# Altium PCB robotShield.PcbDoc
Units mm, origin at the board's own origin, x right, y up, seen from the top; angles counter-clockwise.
Board outline 152.4 x 101.6 mm, 2 copper layers (Top Layer, Bottom Layer); 72 components, 52 nets, 214 pads, 0 vias.
Unrouted connection lines stored in the file: 132.
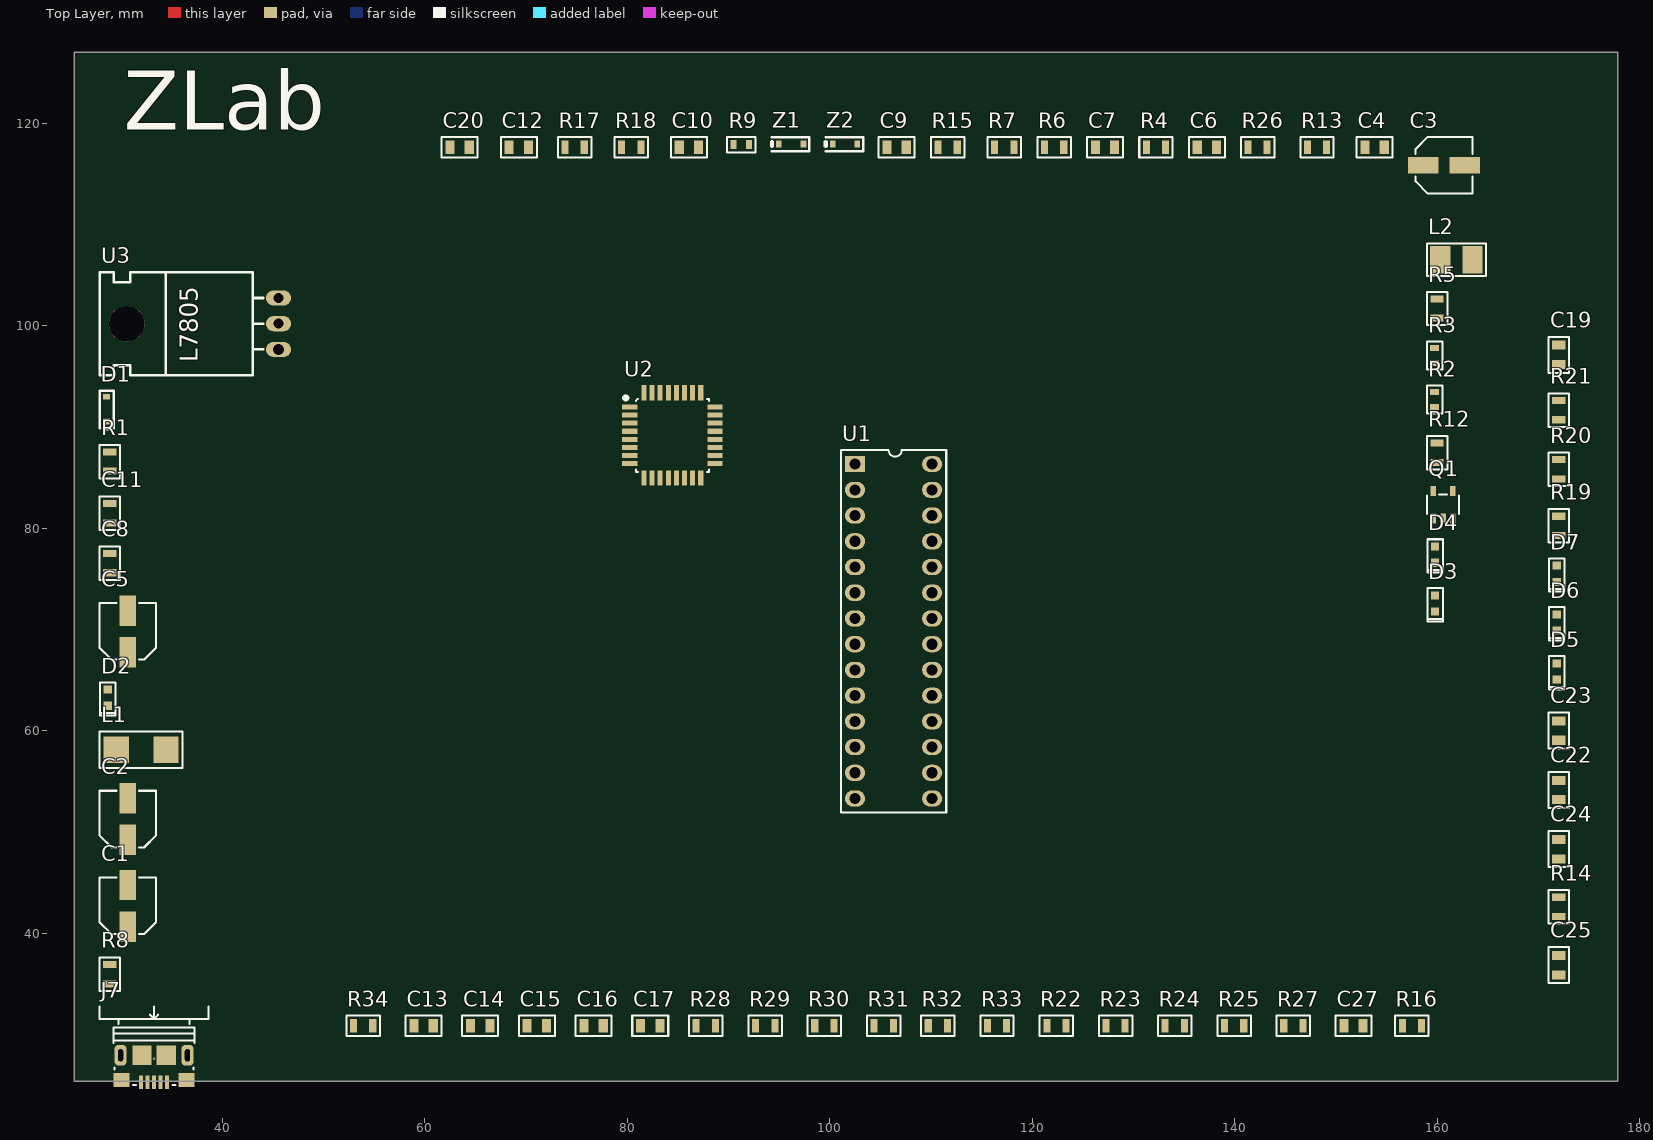
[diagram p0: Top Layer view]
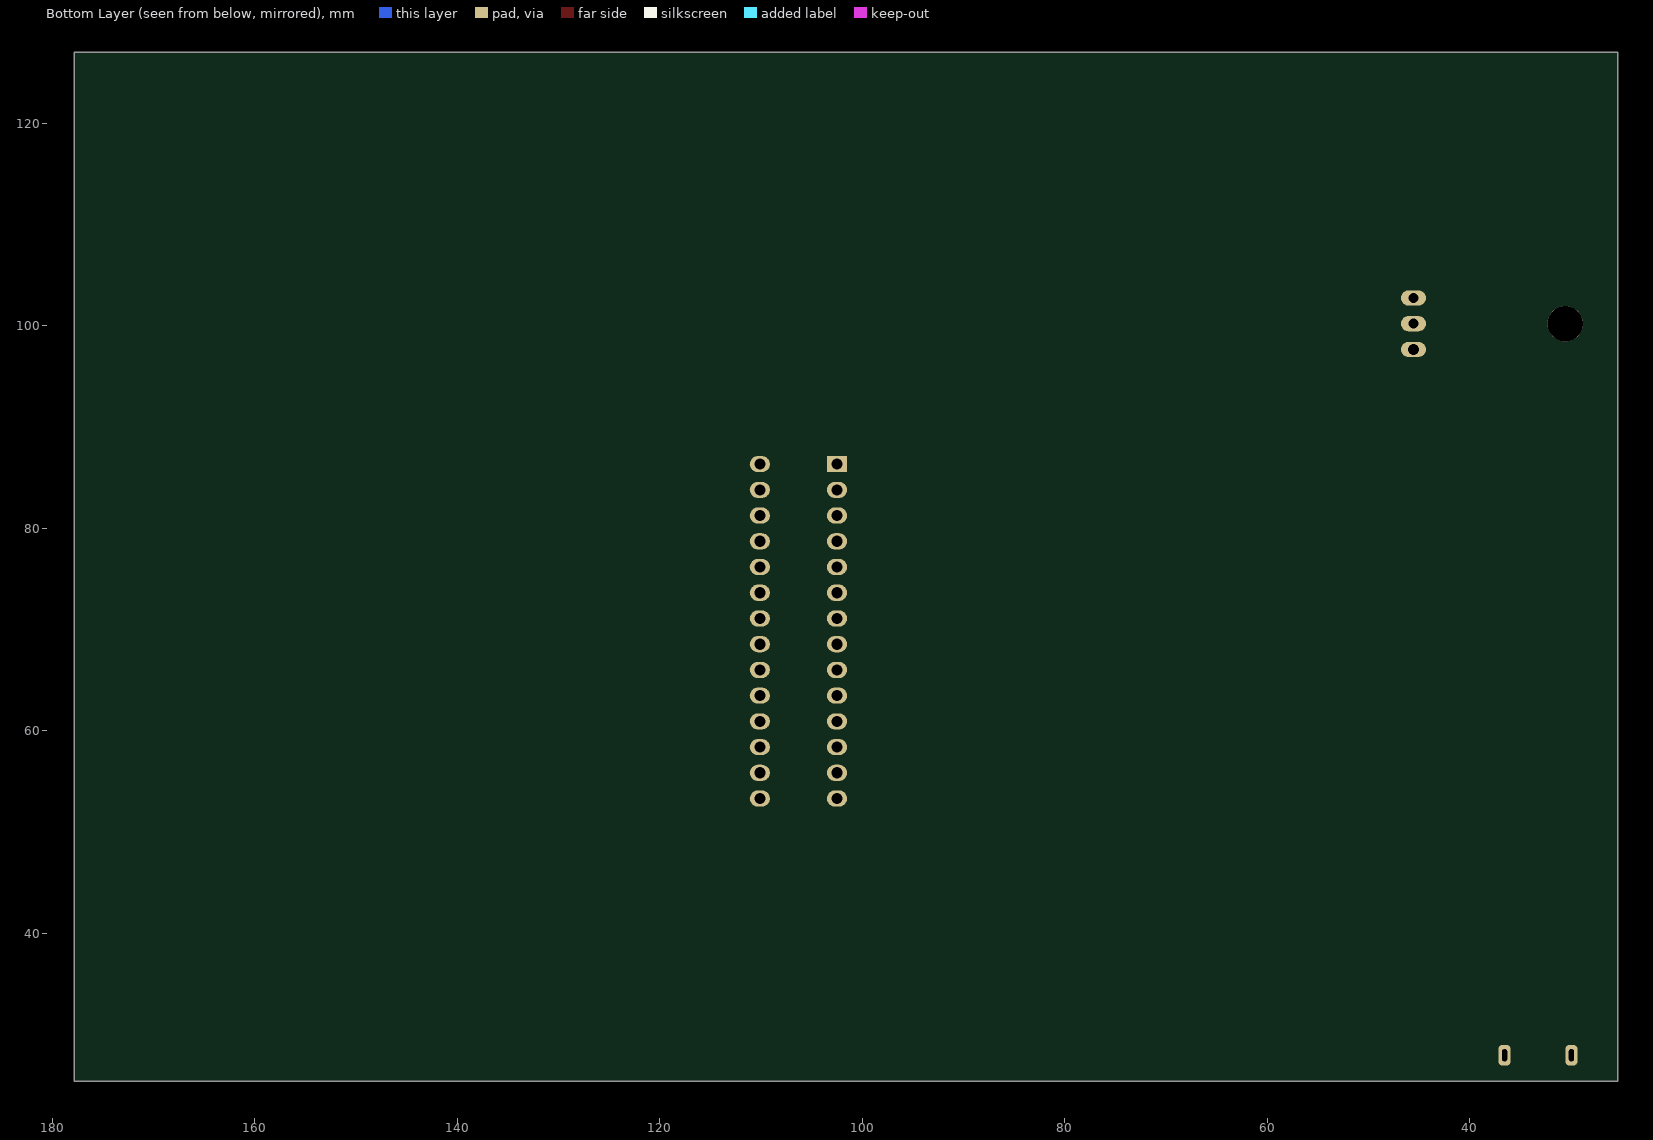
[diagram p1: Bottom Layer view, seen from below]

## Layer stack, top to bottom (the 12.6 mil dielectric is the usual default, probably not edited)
Top Solder: solder mask 0.0102, Solder Resist, Dk 3.5
Top Layer: signal copper 0.0356
Dielectric 1: dielectric 0.32, FR-4, Dk 4.8
Bottom Layer: signal copper 0.0356
Bottom Solder: solder mask 0.0102, Solder Resist, Dk 3.5

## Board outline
25.4,25.4 177.8,25.4 177.8,127 25.4,127

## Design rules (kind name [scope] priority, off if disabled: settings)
Clearance [All] p1: gap=0.254 ignorepadtopadclearanceinfootprint=FALSE
PolygonConnect [All] p1: connectstyle=Relief reliefconductorwidth=0.254 reliefentries=4 polygonreliefangle="90 Angle" airgapwidth=0.254
RoutingVias [All] p1: holewidth=0.711 width=1.27 viastyle="Through Hole" minholewidth=0.711 minwidth=1.27 maxholewidth=0.711 maxwidth=1.27
SolderMaskExpansion [All] p1: expansion=0.102 istentingtop=FALSE
Width [All] p1: maxlimit=0.254 minlimit=0.254 preferedwidth=0.254
30 further rules are at their usual default settings.

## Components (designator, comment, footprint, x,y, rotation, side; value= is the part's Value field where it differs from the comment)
C1 "100u / 10V" C_ALU_C_SIZE 30.683,42.723 r90 top
C2 "100u / 10V" C_ALU_C_SIZE 30.683,51.283 r90 top
C3 "10uF / 16V" C_ALU_C_SIZE 160.655,115.849 r0 top
C4 "100n" C0805 153.797,117.627 r0 top
C5 "10u" C_ALU_C_SIZE 30.683,69.825 r90 top
C6 "100n" C0805 137.236,117.627 r0 top
C7 "1u" C0805 127.178,117.627 r0 top
C8 "100nF" R0805 28.905,76.556 r90 top
C9 "18p" C0805 106.604,117.627 r0 top
C10 "18p" C0805 86.081,117.627 r0 top
C11 "100nF" R0805 28.905,81.483 r90 top
C12 "100n" C0805 69.291,117.627 r0 top
C13 "Cap" C0805 59.893,30.886 r0 top value=100nF
C14 "Cap" C0805 65.481,30.886 r0 top value=100nF
C15 "Cap" C0805 71.069,30.886 r0 top value=100nF
C16 "Cap" C0805 76.683,30.886 r0 top value=100nF
C17 "Cap" C0805 82.271,30.886 r0 top value=100nF
C19 "10uF / 16V" C0805 171.983,97.13 r90 top
C20 "100n" C0805 63.449,117.627 r0 top
C22 "10uF / 16V" C0805 171.983,54.153 r90 top
C23 "100n" C0805 171.983,60.02 r90 top
C24 "100n" C0805 171.983,48.311 r90 top
C25 "18p" C0805 171.983,36.855 r90 top
C27 "18p" C0805 151.714,30.886 r0 top
D1 "Diode" SOD323 28.6,91.77 r90 top
D2 "Power" LED_0603 28.702,63.271 r90 top
D3 "" LED_0603 159.766,72.568 r90 top
D4 "" LED_0603 159.766,77.394 r90 top
D5 "GREEN" LED_0603 171.78,65.862 r90 top
D6 "YELLOW" LED_0603 171.78,70.688 r90 top
D7 "RED" LED_0603 171.78,75.514 r90 top
J7 "" 10118193 33.274,27.965 r180 top
L1 "2u2 / 2A" ABM7_v1_1_BIG 32.004,58.141 r180 top
L2 "Ferrite Bead" C1210_IND 161.874,106.528 r180 top
Q1 "BC817" DBV_SOT_23_5 160.553,82.321 r90 top
R1 "560" R0805 28.905,86.589 r90 top
R2 "560R" R0603 159.715,92.71 r90 top
R3 "560R" R0603 159.715,97.053 r90 top
R4 "10k" R0805 132.207,117.627 r0 top
R5 "1K" R0805 159.969,101.702 r90 top value=3.9R
R6 "22R" R0805 122.149,117.627 r0 top
R7 "22R" R0805 117.221,117.627 r0 top
R8 "0R" R0805 28.905,35.966 r90 top
R9 "1M" R0603 91.262,117.881 r0 top
R12 "1K" R0805 159.969,87.452 r90 top
R13 "10K" R0805 148.107,117.627 r0 top
R14 "10k" R0805 171.983,42.621 r90 top
R15 "Res1" R0805 111.633,117.627 r0 top value=4.7k
R16 "1M" R0805 157.48,30.886 r0 top
R17 "4.7K" R0805 74.803,117.627 r0 top
R18 "4.7K" R0805 80.391,117.627 r0 top
R19 "560R" R0805 171.983,80.239 r90 top
R20 "560R" R0805 171.983,85.827 r90 top
R21 "560R" R0805 171.983,91.669 r90 top
R22 "0.22OHM-1_4W-1%(0805)" R0805 122.377,30.886 r0 top
R23 "0.22OHM-1_4W-1%(0805)" R0805 128.219,30.886 r0 top
R24 "0.22OHM-1_4W-1%(0805)" R0805 134.061,30.886 r0 top
R25 "0.22OHM-1_4W-1%(0805)" R0805 139.929,30.886 r0 top
R26 "0R" R0805 142.24,117.627 r0 top
R27 "0.22OHM-1_4W-1%(0805)" R0805 145.771,30.886 r0 top
R28 "3.3K" R0805 87.757,30.886 r0 top
R29 "" R0805 93.624,30.886 r0 top value=1K
R30 "" R0805 99.466,30.886 r0 top value=1K
R31 "" R0805 105.334,30.886 r0 top value=1K
R32 "" R0805 110.668,30.886 r0 top value=1K
R33 "" R0805 116.51,30.886 r0 top value=1K
R34 "2.4K" R0805 53.924,30.886 r0 top
U1 "ATMEGA328P-PU" 28_DIP_7.62mm 102.489,86.335 r0 top
U2 "ATMEGA16U2-AU" TQFP32 84.455,89.179 r0 top
U3 "LM7805" L7805 45.568,97.663 r90 top
Z1 "CG0603MLC-05E" SOD323 96.19,117.932 r0 top
Z2 "CG0603MLC-05E" SOD323 101.498,117.932 r0 top

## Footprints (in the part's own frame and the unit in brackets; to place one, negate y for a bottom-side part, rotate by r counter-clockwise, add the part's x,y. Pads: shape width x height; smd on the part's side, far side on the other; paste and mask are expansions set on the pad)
28_DIP_7.62mm [mm] "Creator MM"
  rect 2x1.6 hole 1.1: 1(0,0)
  oval 2x1.6 hole 1.1: 2(0,-2.54) 3(0,-5.08) 4(0,-7.62) 5(0,-10.16) 6(0,-12.7) 7(0,-15.24) 8(0,-17.78) 9(0,-20.32) 10(0,-22.86) 11(0,-25.4) 12(0,-27.94) 13(0,-30.48) 14(0,-33.02) 15(7.62,-33.02) 16(7.62,-30.48) 17(7.62,-27.94) 18(7.62,-25.4) 19(7.62,-22.86) 20(7.62,-20.32) 21(7.62,-17.78) 22(7.62,-15.24) 23(7.62,-12.7) 24(7.62,-10.16) 25(7.62,-7.62) 26(7.62,-5.08) 27(7.62,-2.54) 28(7.62,0)
  silkscreen extent -1.39,-34.41 9.01,1.39, body extent -0.13,-34.48 7.75,1.46, height 6.15
10118193 [mm] "Creator MM"
  rect 0.4x1.35 smd mask+0.05: 1(-1.3,2.675) 2(-0.65,2.675) 3(0,2.675) 4(0.65,2.675) 5(1.3,2.675)
  rect 1.6x1.4 smd: 6(-3.2,2.45) 7(3.2,2.45)
  rrect60% 1.2x2 hole 0.5 slot 1.2 at 90 deg: 8(-3.3,0) 9(3.3,0)
  rect 1.9x1.9 smd paste-10: 10(-1.2,0) 11(1.2,0)
  silkscreen extent -5.4,-4.8 5.4,2.95, body extent -3.93,-2.76 3.93,2.9, height 2.85
ABM7_v1_1_BIG [mm] "Made longer for hand soldering"
  rect 2.5x2.6 smd: 1(-2.45,0) 2(2.45,0)
  silkscreen extent -4.1,-1.8 4.1,1.8, body extent -3.1,-1.85 3.1,1.85, height 1.45
C0805 [mm]
  rect 0.9x1.3 smd: 1(-0.95,0) 2(0.95,0)
  silkscreen extent -1.78,-1.02 1.78,1.02, body extent -1,-0.6 1,0.6, height 1.5
C1210_IND [mm] "INDUCTOR"
  rect 2x2.7 smd: 1(-1.6,0) 2(1.6,0)
  silkscreen extent -2.9,-1.6 2.9,1.6, body extent -1.6,-1.25 1.6,1.25, height 2.5
C_ALU_C_SIZE [mm] "Creator MM"
  rect 3x1.6 smd: 1(-2.05,0) 2(2.05,0)
  silkscreen extent -2.8,-2.8 2.8,2.8, body extent -3,-2.65 3,2.65, height 6.42
DBV_SOT_23_5 [mm]
  rect 1x0.55 smd: 1(-1.35,0.95) 2(-1.35,0) 3(-1.35,-0.95) 4(1.35,-0.95) 5(1.35,0.95)
  silkscreen extent -0.9,-1.59 1.02,1.59, body extent -1.65,-1.69 1.78,1.69, height 1.45
L7805 [mm]
  oval 1.5x2.5 hole 1.1 paste-2539.97 mask+0.102: 1(0,0)
  oval 1.5x2.5 hole 1 paste-2539.97 mask+0.102: 2(2.54,0)
  oval 1.5x2.5 hole 1 paste-2539.97 mask+0.051: 3(5.08,0)
  round 3.5 hole 3.5 unplated paste-2539.97: ""(2.54,14.986)
  silkscreen extent -2.55,1.52 7.61,17.66
LED_0603 [mm]
  rect 0.8x0.8 smd: 1(-0.8,0) 2(0.8,0)
  silkscreen extent -1.78,-0.76 1.52,0.76, body extent -0.85,-0.4 0.85,0.4, height 0.66
R0603 [mm]
  rect 0.6x0.9 smd: 1(-0.75,0) 2(0.75,0)
  silkscreen extent -1.4,-0.76 1.4,0.76, body extent -0.8,-0.42 0.8,0.42, height 0.8
R0805 [mm]
  rect 0.7x1.3 smd: 1(-0.95,0) 2(0.95,0)
  silkscreen extent -1.65,-1.02 1.65,1.02, body extent -1,-0.6 1,0.6, height 0.7
SOD323 [mil]
  rect 22x27 smd mask+3: 1(-48,0) 2(48,0)
  silkscreen extent -75,-28 71,28, body extent -49,-25 49,25, height 39
TQFP32 [mm] "Creator MM"
  rect 1.5x0.5 smd mask+0.06: 1(-4.2,2.8) 2(-4.2,2) 3(-4.2,1.2) 4(-4.2,0.4) 5(-4.2,-0.4) 6(-4.2,-1.2) 7(-4.2,-2) 8(-4.2,-2.8) 17(4.2,-2.8) 18(4.2,-2) 19(4.2,-1.2) 20(4.2,-0.4) 21(4.2,0.4) 22(4.2,1.2) 23(4.2,2) 24(4.2,2.8)
  rect 0.5x1.5 smd mask+0.06: 9(-2.8,-4.2) 10(-2,-4.2) 11(-1.2,-4.2) 12(-0.4,-4.2) 13(0.4,-4.2) 14(1.2,-4.2) 15(2,-4.2) 16(2.8,-4.2) 25(2.8,4.2) 26(2,4.2) 27(1.2,4.2) 28(0.4,4.2) 29(-0.4,4.2) 30(-1.2,4.2) 31(-2,4.2) 32(-2.8,4.2)
  silkscreen extent -4.7,-3.6 3.6,3.8, body extent -4.6,-4.6 4.6,4.6, height 1.2

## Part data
C1 C2: library part EEE-1AA101WR, "CAP ALUM 100UF 10V 20% SMD", Capacitance=100µF, ESR (Equivalent Series Resistance)=-, Lifetime @ Temp.="1000 Hrs @ 85°C", Manufacturer="Panasonic Electronic Components", Operating Temperature="-40°C ~ 85°C", Package / Case="Radial, Can - SMD", Ripple Current=50mA, Supplier Part Number 1=PCE3867CT-ND, Tolerance=±20%, Voltage Rating=10V
C3 C19 C22: library part C2012X5R1C106M, "CAP CER 10UF 16V 20% X5R 0805", Capacitance=10µF, Manufacturer="TDK Corporation", Manufacturer Part Number=C2012X5R1C106M/1.25, Operating Temperature="-55°C ~ 85°C", Package / Case="0805 (2012 Metric)", Ratings=-, Supplier Part Number 1=445-4115-1-ND, Temperature Coefficient=X5R, Tolerance=±20%, Voltage - Rated=16V
C4 C6 C12 C20 C23 C24: library part C2012X7R1H104K085AA, "CAP CER 0.1UF 50V 10% X7R 0805", Capacitance=0.1µF, Manufacturer="TDK Corporation", Operating Temperature="-55°C ~ 125°C", Package / Case="0805 (2012 Metric)", Ratings=-, Supplier Part Number 1=445-7534-1-ND, Temperature Coefficient=X7R, Tolerance=±10%, Voltage - Rated=50V
C5 R22 R23 R24 R25 R27 U3: Manufacturer Part=?
C7: library part C2012X5R1E105K125AA, "CAP CER 1UF 25V 10% X5R 0805", Capacitance=1µF, Manufacturer="TDK Corporation", Operating Temperature="-55°C ~ 85°C", Package / Case="0805 (2012 Metric)", Ratings=-, Supplier Part Number 1=445-1419-1-ND, Temperature Coefficient=X5R, Tolerance=±10%, Voltage - Rated=25V
C8 C11: library part 0.1u, Manufacturer Part=?
C9 C10 C25 C27: library part C0805C180J5GACTU, "CAP CER 18PF 50V 5% NP0 0805", Capacitance=18pF, Manufacturer=Kemet, Operating Temperature="-55°C ~ 125°C", Package / Case="0805 (2012 Metric)", Ratings=-, Supplier Part Number 1=399-1112-1-ND, Temperature Coefficient="C0G, NP0", Tolerance=±5%, Voltage - Rated=50V
C13 C14 C15 C16 C17: "Capacitor"
D1: "Default Diode"
D2: library part RED, Manufacturer Part=?
D3 D4: library part "LO L29K-H2K1-24-Z", "LED SMARTLED ORANGE 606NM 0603", Color=Orange, Current - Test=2mA, Luminous Flux @ Current - Test="25 mlm", Manufacturer="OSRAM Opto Semiconductors Inc", Millicandela Rating=6.3mcd, Package / Case="0603 (1608 Metric)", Supplier Part Number 1=475-2740-1-ND, Voltage - Forward (Vf) Typ=1.8V
D5 D6 D7: library part "LO L29K-H2K1-24-Z", Color=Orange, Current - Test=2mA, Luminous Flux @ Current - Test="25 mlm", Manufacturer="OSRAM Opto Semiconductors Inc", Millicandela Rating=6.3mcd, Package / Case="0603 (1608 Metric)", Supplier Part Number 1=475-2740-1-ND, Voltage - Forward (Vf) Typ=1.8V
J7: library part 10118193-0001LF, "CONN USB MICRO B RECPT SMT R/A", Manufacturer=FCI, Supplier Part Number 1=609-4616-1-ND
L1: library part L1210R2R2MDWIT, "FIXED IND 2.2UH 2A 80 MOHM SMD", Current - Saturation=-, Current Rating=2A, DC Resistance (DCR)="80 mOhm", Frequency - Self Resonant=190MHz, Frequency - Test=100kHz, Inductance=2.2µH, Manufacturer=Kemet, Operating Temperature="-40°C ~ 105°C", Package / Case="1210 (3225 Metric)", Supplier Device Package=1210, Supplier Part Number 1=399-9598-1-ND, Tolerance=±20%
L2: library part L1210R2R2MDWIT, Current - Saturation=-, Current Rating=2A, DC Resistance (DCR)="80 mOhm", Frequency - Self Resonant=190MHz, Frequency - Test=100kHz, Inductance=2.2µH, Manufacturer=Kemet, Operating Temperature="-40°C ~ 105°C", Package / Case="1210 (3225 Metric)", Supplier Device Package=1210, Supplier Part Number 1=399-9598-1-ND, Tolerance=±20%
Q1: library part NPN, "NPN Transistor"
R1: library part 10k, Manufacturer Part=?
R2 R3 R19 R20 R21 R28 R34: library part RC0805FR-07560RL, "RES SMD 560 OHM 1% 1/8W 0805", Manufacturer=Yageo, Operating Temperature="-55°C ~ 155°C", Package / Case="0805 (2012 Metric)", Power (Watts)="0.125W, 1/8W", Resistance (Ohms)=560, Supplier Device Package=0805, Supplier Part Number 1=311-560CRCT-ND, Temperature Coefficient=±100ppm/°C, Tolerance=±1%
R4 R14: library part RC0805FR-0710KL, "RES SMD 10K OHM 1% 1/8W 0805", Manufacturer=Yageo, Operating Temperature="-55°C ~ 155°C", Package / Case="0805 (2012 Metric)", Power (Watts)="0.125W, 1/8W", Supplier Device Package=0805, Supplier Part Number 1=311-10.0KCRCT-ND, Temperature Coefficient=±100ppm/°C, Tolerance=±1%
R5 R12 R13 R29 R30 R31 R32 R33: library part Res1, "Resistor"
R6 R7: library part RC0805FR-0722RL, "RES SMD 22 OHM 1% 1/8W 0805", Manufacturer=Yageo, Operating Temperature="-55°C ~ 155°C", Package / Case="0805 (2012 Metric)", Power (Watts)="0.125W, 1/8W", Resistance (Ohms)=22, Supplier Device Package=0805, Supplier Part Number 1=311-22.0CRCT-ND, Temperature Coefficient=±100ppm/°C, Tolerance=±1%
R8 R26: library part RC0805JR-070RL, "RES 0.0 OHM 1/8W 0805 SMD", Manufacturer=Yageo, Package / Case="0805 (2012 Metric)", Power (Watts)="0.125W, 1/8W", Resistance (Ohms)=0.0, Supplier Part Number=311-0.0ARCT-ND, Temperature Coefficient=-, Tolerance=Jumper
R9 R16: library part RC0805FR-071ML, "RES SMD 1M OHM 1% 1/8W 0805", Manufacturer=Yageo, Operating Temperature="-55°C ~ 155°C", Package / Case="0805 (2012 Metric)", Power (Watts)="0.125W, 1/8W", Supplier Device Package=0805, Supplier Part Number 1=311-1.00MCRCT-ND, Temperature Coefficient=±100ppm/°C, Tolerance=±1%
R15: "Resistor"
R17 R18: library part RES1
U1: "IC MCU 8BIT 32KB FLASH 28DIP", Manufacturer=Atmel, Operating Temperature="-40°C ~ 85°C", Package / Case="28-DIP (0.300\", 7.62mm)", Supplier Device Package=28-PDIP, Supplier Part Number 1=ATMEGA328P-PU-ND, Voltage - Supply (Vcc/Vdd)="1.8 V ~ 5.5 V"
U2: "IC MCU 8BIT 16KB FLASH 32TQFP", Manufacturer=Atmel, Operating Temperature="-40°C ~ 85°C", Package / Case=32-TQFP, Supplier Device Package="32-TQFP (7x7)", Supplier Part Number 1=ATMEGA16U2-AU-ND, Voltage - Supply (Vcc/Vdd)="2.7 V ~ 5.5 V"
Z1 Z2: "VARISTOR 0603", Current - Surge=-, Manufacturer="Bourns Inc.", Maximum DC Volts=5VDC, Package / Case="0603 (1608 Metric)", Supplier Part Number 1=CG0603MLC-05ECT-ND

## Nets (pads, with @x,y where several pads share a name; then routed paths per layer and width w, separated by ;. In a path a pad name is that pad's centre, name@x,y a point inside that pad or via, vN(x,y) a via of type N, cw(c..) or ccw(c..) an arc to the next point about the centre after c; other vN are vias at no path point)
16U2_RX_LED: D4.1 U2.10
16U2_RXD: U2.8
16U2_TX_LED: D3.1 U2.11
16U2_TXD: U2.9
328P_RESETn: R14.1 U1.1
+5V: C2.1 C3.1 C4.1 C6.1 C12.2 C19.1 C20.1 C22.1 C23.1 C24.1 L1.2 R1.2 R2.2 R3.2 R4.2 R5.1 R14.2 R15.1 R17.1 R18.2 R19.2 R20.2 R21.2 R22.2 R23.2 R24.2 R25.2 R26.2 R27.2 U1.7 U1.20 U1.21 U2.4 U2.31 U2.32
+12Battery: D1.1 R28.2
ADC-Input: R28.1 R34.2 U1.23
AGND: C22.2 C24.2 L2.2 R34.1
Buzzer: R12.2 U1.13
CON_USB_N: J7.2 R6.1 Z1.2
CON_USB_P: J7.3 R7.1 Z2.2
GND: C1.2 C2.2 C3.2 C4.2 C5.2 C6.2 C7.1 C8.1 C9.1 C10.1 C11.1 C12.1 C13.1 C14.1 C15.1 C16.1 C17.1 C19.2 C20.2 C25.1 C27.1 J7.5 J7.6 J7.7 J7.8 J7.9 J7.10 J7.11 Q1.2 R8.2 R13.2 U1.8 U1.22 U2.3 U2.28 U3.2 Z1.1 Z2.1
I2C-SCL: R17.2 U1.28
I2C-SDA: R18.1 U1.27
LED-Green: D5.1 U1.19
LED-Red: D7.1 U1.17
LED-Yellow: D6.1 U1.18
NetC1_1: C1.1 J7.1 L1.1
NetC5_1: C5.1 C8.2 D1.2 U3.1
NetC7_2: C7.2 R26.1 U2.27
NetC9_2: C9.2 R9.2 U2.2
NetC10_2: C10.2 R9.1 U2.1
NetC11_2: C11.2 U3.3
NetC13_2: C13.2 R22.1 R29.2
NetC25_2: C25.2 R16.2 U1.10
NetC27_2: C27.2 R16.1 U1.9
NetD2_A: R1.1
NetD3_2: D3.2 R2.1
NetD4_2: D4.2 R3.1
NetD5_2: D5.2 R19.1
NetD6_2: D6.2 R20.1
NetD7_2: D7.2 R21.1
NetJ7_4: J7.4 R8.1
NetQ1_1: Q1.1 R12.1 R13.1
NetQ1_3: Q1.3
NetR4_1: R4.1 U2.24
NetR5_2: R5.2
NetR10_2: U1.2
NetR11_2: U1.3
NetR29_1: R29.1
NetR30_1: R30.1
NetR31_1: R31.1
NetR32_1: R32.1
NetR33_1: R33.1
"Switch 1": U1.4
"Switch 2": C14.2 R23.1 R30.2 U1.5
"Switch 3": C15.2 R24.1 R31.2 U1.6
"Switch 4": C16.2 R25.1 R32.2 U1.11
"Switch 5": C17.2 R27.1 R33.2 U1.12
USB_N: R6.2 U2.30
USB_P: R7.2 R15.2 U2.29
pads on no net: C23.2 D2.1 D2.2 L2.1 Q1.4 Q1.5 U1.14 U1.15 U1.16 U1.24 U1.25 U1.26 U2.5 U2.6 U2.7 U2.12 U2.13 U2.14 U2.15 U2.16 U2.17 U2.18 U2.19 U2.20 U2.21 U2.22 U2.23 U2.25 U2.26 U3.

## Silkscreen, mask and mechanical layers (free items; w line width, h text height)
Top Overlay:
  text "ZLab" at 30.269,117.412 h10
Mechanical 1:
  lines w1.016: 64.572,42.126 144.572,42.126 144.572,102.126 64.572,102.126 64.572,42.126

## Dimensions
64.572,102.126 to 64.572,42.126 on Top Overlay
144.572,102.126 to 64.572,102.126 on Top Overlay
